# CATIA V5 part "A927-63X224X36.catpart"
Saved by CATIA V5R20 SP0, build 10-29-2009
Part number: A927-63X224X36
Source: Unknown
Property "A": "36.000"
Property "ARTICLENO": "A927-63X224X36"
Property "BOMINFO": "A927-63X224X36"
Property "CODE": "A927-63X224X36"
Property "CREATOR": "CADENAS GmbH"
Property "D": "14.000"
Property "D1": "20.000"
Property "F": "18.000"
Property "FORM": "A"
Property "L": "224.000"
Property "L1": "90.000"
Property "L2": "20.000"
Property "L3": "50.000"
Property "LINA": "A927-63X224X36"
Property "NB": "A927-63X224X36"
Property "NBSYN": "$CODE."
Property "NN": "A927"
Property "NT": "VDI 3387 Removable Die Heels, steel and self-lubricating"
Property "R": "16.000"
Property "S": "36.000"
Property "SUPPLIER": "CF"
Property "T": "16.000"
Property "W": "63.000"
Bounding box of the stored display mesh (mm): x -31.5 to 31.5, y 0 to 224, z -36 to 0
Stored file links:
  C:\Users\borellobunino\Desktop\3D X SITO CF\A927\GSB_OILLESS_G2290506322436\CATIAV5\A927-63X224X36.catpart
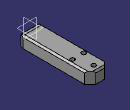
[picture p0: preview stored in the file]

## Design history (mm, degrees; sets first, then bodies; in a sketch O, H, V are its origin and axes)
Body1 "Geometry.1" (main body)
  Solid1 "A927-63X224X36.catpart": solid without history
